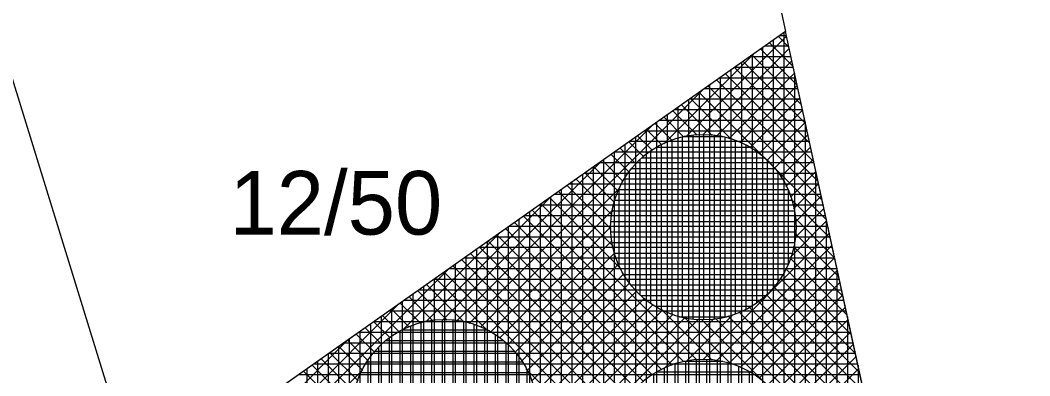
# Model space of a CAD drawing. Extents: x -566461 to -565198, y -1096301 to -1095707.
# Drawn here: x -566390.07 to -566371.02, y -1095849.12 to -1095842.41 of the extents above; entities that cross this region are included whole.
import ezdxf

# ---------------------------------------------------------------- set-up
doc = ezdxf.new("R2010")
doc.units = 0
for name, color, linetype in [('Vrstva 1', 7, 'Continuous'), ('Vrstva 40', 7, 'Continuous'), ('Vrstva 41', 7, 'Continuous'), ('Vrstva 42', 7, 'Continuous'), ('Vrstva 43', 7, 'Continuous'), ('Vrstva 44', 7, 'Continuous')]:
    doc.layers.add(name, color=color, linetype=linetype)

msp = doc.modelspace()

# ---------------------------------------------------------------- linework, layer by layer
at = {"layer": 'Vrstva 1'}
for p, q in [((-566376.68, -1095837.78), (-566375.63, -1095842.63)), ((-566387.83, -1095851.23), (-566391.07, -1095840.75)), ((-566375.63, -1095842.63), (-566387.83, -1095851.23)), ((-566371.02, -1095863.83), (-566375.63, -1095842.63))]:
    msp.add_line(p, q, dxfattribs=at)
at = {"layer": 'Vrstva 41'}
for p, q in [((-566375.611, -1095842.717), (-566377.507, -1095844.612)), ((-566375.763, -1095842.724), (-566375.567, -1095842.92)), ((-566375.561, -1095842.949), (-566377.192, -1095844.581)), ((-566376.095, -1095842.958), (-566375.41, -1095843.643)), ((-566375.929, -1095842.841), (-566375.488, -1095843.282)), ((-566376.231, -1095843.053), (-566377.927, -1095844.75)), ((-566376.261, -1095843.075), (-566375.331, -1095844.005)), ((-566375.51, -1095843.181), (-566376.929, -1095844.6)), ((-566376.593, -1095843.309), (-566375.174, -1095844.728)), ((-566376.427, -1095843.192), (-566375.252, -1095844.366)), ((-566376.759, -1095843.426), (-566375.095, -1095845.089)), ((-566375.46, -1095843.414), (-566376.696, -1095844.65)), ((-566377.09, -1095843.66), (-566374.938, -1095845.812)), ((-566376.925, -1095843.543), (-566375.017, -1095845.45)), ((-566375.409, -1095843.646), (-566376.487, -1095844.724)), ((-566377.189, -1095843.729), (-566381.595, -1095848.135)), ((-566377.422, -1095843.893), (-566376.654, -1095844.662)), ((-566377.256, -1095843.776), (-566374.859, -1095846.173)), ((-566375.359, -1095843.878), (-566376.3, -1095844.82)), ((-566377.588, -1095844.01), (-566377.01, -1095844.588)), ((-566377.92, -1095844.244), (-566377.545, -1095844.619)), ((-566377.754, -1095844.127), (-566377.296, -1095844.586)), ((-566375.308, -1095844.111), (-566376.131, -1095844.933)), ((-566378.148, -1095844.405), (-566381.83, -1095848.087)), ((-566378.252, -1095844.478), (-566377.962, -1095844.768)), ((-566378.086, -1095844.361), (-566377.764, -1095844.683)), ((-566375.257, -1095844.343), (-566375.979, -1095845.064)), ((-566378.418, -1095844.595), (-566378.141, -1095844.872)), ((-566375.207, -1095844.575), (-566375.842, -1095845.211)), ((-566378.749, -1095844.829), (-566378.448, -1095845.131)), ((-566378.584, -1095844.712), (-566378.302, -1095844.993)), ((-566375.156, -1095844.808), (-566375.722, -1095845.374)), ((-566378.915, -1095844.946), (-566378.577, -1095845.284)), ((-566375.106, -1095845.04), (-566375.62, -1095845.554)), ((-566379.106, -1095845.08), (-566382.098, -1095848.072)), ((-566379.247, -1095845.18), (-566378.782, -1095845.645)), ((-566379.081, -1095845.063), (-566378.689, -1095845.455)), ((-566379.579, -1095845.414), (-566378.903, -1095846.089)), ((-566379.413, -1095845.297), (-566378.855, -1095845.855)), ((-566375.055, -1095845.272), (-566375.536, -1095845.753)), ((-566378.75, -1095845.573), (-566381.385, -1095848.207)), ((-566379.745, -1095845.531), (-566378.918, -1095846.357)), ((-566375.005, -1095845.505), (-566375.475, -1095845.975)), ((-566380.065, -1095845.756), (-566382.416, -1095848.107)), ((-566380.077, -1095845.765), (-566378.725, -1095847.117)), ((-566379.911, -1095845.648), (-566378.883, -1095846.675)), ((-566375.522, -1095845.794), (-566374.781, -1095846.535)), ((-566374.954, -1095845.737), (-566375.445, -1095846.227)), ((-566378.888, -1095845.993), (-566381.195, -1095848.301)), ((-566380.408, -1095845.998), (-566377.546, -1095848.861)), ((-566380.243, -1095845.881), (-566377.296, -1095848.828)), ((-566374.904, -1095845.969), (-566375.462, -1095846.527)), ((-566380.574, -1095846.115), (-566377.765, -1095848.925)), ((-566374.853, -1095846.202), (-566375.534, -1095846.883)), ((-566375.448, -1095846.15), (-566374.702, -1095846.896)), ((-566378.919, -1095846.308), (-566381.024, -1095848.413)), ((-566380.906, -1095846.349), (-566378.141, -1095849.114)), ((-566380.74, -1095846.232), (-566377.962, -1095849.01)), ((-566381.023, -1095846.432), (-566382.857, -1095848.266)), ((-566381.238, -1095846.583), (-566378.448, -1095849.373)), ((-566381.072, -1095846.466), (-566378.303, -1095849.235)), ((-566378.9, -1095846.571), (-566380.87, -1095848.542)), ((-566374.803, -1095846.434), (-566377.191, -1095848.823)), ((-566375.452, -1095846.43), (-566374.624, -1095847.258)), ((-566381.404, -1095846.7), (-566378.577, -1095849.527)), ((-566374.752, -1095846.666), (-566376.928, -1095848.842)), ((-566375.479, -1095846.685), (-566374.545, -1095847.619)), ((-566381.736, -1095846.934), (-566378.781, -1095849.888)), ((-566381.57, -1095846.817), (-566378.689, -1095849.698)), ((-566378.85, -1095846.804), (-566380.733, -1095848.687)), ((-566374.702, -1095846.899), (-566376.696, -1095848.893)), ((-566375.543, -1095846.904), (-566374.467, -1095847.981)), ((-566381.982, -1095847.107), (-566387.422, -1095852.548)), ((-566381.902, -1095847.051), (-566378.853, -1095850.099)), ((-566378.776, -1095847.013), (-566380.612, -1095848.849)), ((-566374.651, -1095847.131), (-566376.487, -1095848.967)), ((-566375.628, -1095847.102), (-566374.388, -1095848.342)), ((-566382.233, -1095847.285), (-566381.242, -1095848.277)), ((-566382.067, -1095847.168), (-566378.902, -1095850.334)), ((-566378.68, -1095847.2), (-566380.508, -1095849.028)), ((-566375.732, -1095847.281), (-566374.309, -1095848.703)), ((-566382.565, -1095847.519), (-566382.011, -1095848.072)), ((-566382.399, -1095847.402), (-566381.691, -1095848.11)), ((-566378.567, -1095847.369), (-566380.423, -1095849.225)), ((-566378.436, -1095847.521), (-566380.359, -1095849.444)), ((-566374.601, -1095847.363), (-566376.3, -1095849.062)), ((-566375.853, -1095847.442), (-566374.231, -1095849.065)), ((-566382.731, -1095847.636), (-566382.281, -1095848.085)), ((-566378.289, -1095847.658), (-566380.326, -1095849.694)), ((-566376.144, -1095847.717), (-566374.193, -1095849.668)), ((-566374.55, -1095847.596), (-566376.131, -1095849.176)), ((-566375.991, -1095847.588), (-566374.152, -1095849.426)), ((-566382.94, -1095847.783), (-566387.489, -1095852.332)), ((-566383.063, -1095847.87), (-566382.728, -1095848.205)), ((-566382.897, -1095847.753), (-566382.516, -1095848.133)), ((-566377.946, -1095847.88), (-566380.402, -1095850.336)), ((-566378.126, -1095847.778), (-566380.339, -1095849.99)), ((-566377.977, -1095847.865), (-566377.011, -1095848.83)), ((-566376.315, -1095847.829), (-566374.251, -1095849.893)), ((-566374.5, -1095847.828), (-566375.978, -1095849.307)), ((-566377.273, -1095848.055), (-566386.086, -1095856.868)), ((-566383.395, -1095848.103), (-566383.09, -1095848.408)), ((-566377.525, -1095848.025), (-566383.378, -1095853.878)), ((-566377.747, -1095847.964), (-566383.233, -1095853.45)), ((-566383.229, -1095847.986), (-566382.918, -1095848.297)), ((-566376.983, -1095848.049), (-566377.927, -1095848.993)), ((-566377.535, -1095848.023), (-566376.654, -1095848.904)), ((-566376.617, -1095847.966), (-566377.506, -1095848.854)), ((-566377.217, -1095848.058), (-566374.562, -1095850.713)), ((-566376.949, -1095848.043), (-566374.449, -1095850.544)), ((-566376.715, -1095847.995), (-566374.367, -1095850.343)), ((-566376.505, -1095847.922), (-566374.309, -1095850.118)), ((-566374.449, -1095848.06), (-566375.842, -1095849.453)), ((-566383.561, -1095848.22), (-566383.244, -1095848.536)), ((-566374.399, -1095848.293), (-566375.723, -1095849.617)), ((-566383.899, -1095848.459), (-566387.556, -1095852.116)), ((-566383.892, -1095848.454), (-566383.504, -1095848.843)), ((-566383.726, -1095848.337), (-566383.382, -1095848.681)), ((-566384.058, -1095848.571), (-566383.608, -1095849.021)), ((-566374.348, -1095848.525), (-566375.621, -1095849.797)), ((-566384.39, -1095848.805), (-566383.759, -1095849.436)), ((-566384.224, -1095848.688), (-566383.694, -1095849.218)), ((-566374.298, -1095848.757), (-566375.537, -1095849.997)), ((-566383.604, -1095849.013), (-566387.355, -1095852.764)), ((-566384.722, -1095849.039), (-566383.792, -1095849.969)), ((-566384.556, -1095848.922), (-566383.794, -1095849.684)), ((-566380.527, -1095848.992), (-566378.916, -1095850.602)), ((-566374.247, -1095848.989), (-566375.477, -1095850.219))]:
    msp.add_line(p, q, dxfattribs=at)
at = {"layer": 'Vrstva 42'}
msp.add_lwpolyline([(-566383.841, -1095864.127), (-566382.67, -1095860.71), (-566381.61, -1095858.96), (-566380.13, -1095856.89), (-566378.22, -1095854.98), (-566377.21, -1095854.03), (-566376.26, -1095853.18), (-566375.36, -1095851.91), (-566374.4, -1095850.47), (-566374.143, -1095849.47), (-566375.63, -1095842.63), (-566387.83, -1095851.23)], close=True, dxfattribs=at)
at = {"layer": 'Vrstva 43'}
for p, q in [((-566375.729, -1095842.7), (-566375.615, -1095842.7)), ((-566375.66, -1095842.651), (-566375.66, -1095867.101)), ((-566376.06, -1095842.933), (-566376.06, -1095867.383)), ((-566376.013, -1095842.9), (-566375.571, -1095842.9)), ((-566375.86, -1095842.792), (-566375.86, -1095867.242)), ((-566376.297, -1095843.1), (-566375.528, -1095843.1)), ((-566376.26, -1095843.074), (-566376.26, -1095867.524)), ((-566376.58, -1095843.3), (-566375.484, -1095843.3)), ((-566376.46, -1095843.215), (-566376.46, -1095867.665)), ((-566376.864, -1095843.5), (-566375.441, -1095843.5)), ((-566376.86, -1095843.497), (-566376.86, -1095867.947)), ((-566376.66, -1095843.356), (-566376.66, -1095867.806)), ((-566375.46, -1095843.412), (-566375.46, -1095866.96)), ((-566377.148, -1095843.7), (-566375.397, -1095843.7)), ((-566377.06, -1095843.638), (-566377.06, -1095868.088)), ((-566377.432, -1095843.9), (-566375.354, -1095843.9)), ((-566377.26, -1095843.779), (-566377.26, -1095868.229)), ((-566377.715, -1095844.1), (-566375.31, -1095844.1)), ((-566377.66, -1095844.061), (-566377.66, -1095868.511)), ((-566377.46, -1095843.92), (-566377.46, -1095868.37)), ((-566377.86, -1095844.202), (-566377.86, -1095868.652)), ((-566378.26, -1095844.484), (-566378.26, -1095868.934)), ((-566378.06, -1095844.343), (-566378.06, -1095868.793)), ((-566377.999, -1095844.3), (-566375.267, -1095844.3)), ((-566375.26, -1095844.332), (-566375.26, -1095866.819)), ((-566378.46, -1095844.625), (-566378.46, -1095869.075)), ((-566378.283, -1095844.5), (-566375.223, -1095844.5)), ((-566378.66, -1095844.766), (-566378.66, -1095869.216)), ((-566378.567, -1095844.7), (-566375.18, -1095844.7)), ((-566379.06, -1095845.048), (-566379.06, -1095869.498)), ((-566378.86, -1095844.907), (-566378.86, -1095869.357)), ((-566378.85, -1095844.9), (-566375.136, -1095844.9)), ((-566379.26, -1095845.189), (-566379.26, -1095869.639)), ((-566379.134, -1095845.1), (-566375.093, -1095845.1)), ((-566379.46, -1095845.33), (-566379.46, -1095869.78)), ((-566379.418, -1095845.3), (-566375.049, -1095845.3)), ((-566375.06, -1095845.251), (-566375.06, -1095866.678)), ((-566379.86, -1095845.612), (-566379.86, -1095870.062)), ((-566379.701, -1095845.5), (-566375.006, -1095845.5)), ((-566379.66, -1095845.471), (-566379.66, -1095869.921)), ((-566380.06, -1095845.753), (-566380.06, -1095870.203)), ((-566379.985, -1095845.7), (-566374.962, -1095845.7)), ((-566380.269, -1095845.9), (-566374.919, -1095845.9)), ((-566380.26, -1095845.894), (-566380.26, -1095870.344)), ((-566380.66, -1095846.176), (-566380.66, -1095870.626)), ((-566380.553, -1095846.1), (-566374.875, -1095846.1)), ((-566380.46, -1095846.035), (-566380.46, -1095870.485)), ((-566374.86, -1095846.171), (-566374.86, -1095866.537)), ((-566380.86, -1095846.317), (-566380.86, -1095870.767)), ((-566380.836, -1095846.3), (-566374.832, -1095846.3)), ((-566381.12, -1095846.5), (-566374.788, -1095846.5)), ((-566381.06, -1095846.458), (-566381.06, -1095870.908)), ((-566381.46, -1095846.74), (-566381.46, -1095871.19)), ((-566381.404, -1095846.7), (-566374.745, -1095846.7)), ((-566381.26, -1095846.599), (-566381.26, -1095871.049)), ((-566381.687, -1095846.9), (-566374.701, -1095846.9)), ((-566381.66, -1095846.881), (-566381.66, -1095871.331)), ((-566381.971, -1095847.1), (-566374.658, -1095847.1)), ((-566381.86, -1095847.022), (-566381.86, -1095871.472)), ((-566374.66, -1095847.091), (-566374.66, -1095866.396)), ((-566382.26, -1095847.304), (-566382.26, -1095871.754)), ((-566382.255, -1095847.3), (-566374.614, -1095847.3)), ((-566382.06, -1095847.163), (-566382.06, -1095871.613)), ((-566382.539, -1095847.5), (-566374.571, -1095847.5)), ((-566382.46, -1095847.445), (-566382.46, -1095871.895)), ((-566382.822, -1095847.7), (-566374.528, -1095847.7)), ((-566382.66, -1095847.586), (-566382.66, -1095872.036)), ((-566383.106, -1095847.9), (-566374.484, -1095847.9)), ((-566383.06, -1095847.868), (-566383.06, -1095866.651)), ((-566382.86, -1095847.727), (-566382.86, -1095867.298)), ((-566383.39, -1095848.1), (-566374.441, -1095848.1)), ((-566383.26, -1095848.009), (-566383.26, -1095866.004)), ((-566374.46, -1095848.01), (-566374.46, -1095866.255)), ((-566383.66, -1095848.29), (-566383.66, -1095864.711)), ((-566383.46, -1095848.15), (-566383.46, -1095865.358)), ((-566383.86, -1095848.431), (-566383.86, -1095864.065)), ((-566383.673, -1095848.3), (-566374.397, -1095848.3)), ((-566384.06, -1095848.572), (-566384.06, -1095863.418)), ((-566383.957, -1095848.5), (-566374.354, -1095848.5)), ((-566384.46, -1095848.854), (-566384.46, -1095862.125)), ((-566384.26, -1095848.713), (-566384.26, -1095862.772)), ((-566384.241, -1095848.7), (-566374.31, -1095848.7)), ((-566384.66, -1095848.995), (-566384.66, -1095861.478)), ((-566384.525, -1095848.9), (-566374.267, -1095848.9)), ((-566374.26, -1095848.93), (-566374.26, -1095866.114)), ((-566384.808, -1095849.1), (-566374.223, -1095849.1))]:
    msp.add_line(p, q, dxfattribs=at)
msp.add_lwpolyline([(-566375.63, -1095842.63), (-566387.83, -1095851.23), (-566382.85, -1095867.33), (-566382.87, -1095870.81), (-566385.12, -1095873.77), (-566371.02, -1095863.83)], close=True, dxfattribs=at)
at = {"layer": 'Vrstva 44'}
for p, q in [((-566377.77, -1095847.966), (-566377.77, -1095844.674)), ((-566377.57, -1095848.026), (-566377.57, -1095844.616)), ((-566377.544, -1095844.61), (-566376.811, -1095844.61)), ((-566377.37, -1095848.059), (-566377.37, -1095844.582)), ((-566377.17, -1095848.068), (-566377.17, -1095844.571)), ((-566376.97, -1095848.055), (-566376.97, -1095844.583)), ((-566376.77, -1095848.02), (-566376.77, -1095844.621)), ((-566378.061, -1095844.81), (-566376.299, -1095844.81)), ((-566377.97, -1095847.881), (-566377.97, -1095844.759)), ((-566376.57, -1095847.96), (-566376.57, -1095844.682)), ((-566376.37, -1095847.869), (-566376.37, -1095844.77)), ((-566378.37, -1095847.602), (-566378.37, -1095845.037)), ((-566378.338, -1095845.01), (-566376.023, -1095845.01)), ((-566378.17, -1095847.761), (-566378.17, -1095844.879)), ((-566376.17, -1095847.747), (-566376.17, -1095844.893)), ((-566375.97, -1095847.582), (-566375.97, -1095845.057)), ((-566378.53, -1095845.21), (-566375.828, -1095845.21)), ((-566378.674, -1095845.41), (-566375.688, -1095845.41)), ((-566378.57, -1095847.38), (-566378.57, -1095845.259)), ((-566375.77, -1095847.355), (-566375.77, -1095845.286)), ((-566378.778, -1095845.61), (-566375.581, -1095845.61)), ((-566378.77, -1095847.05), (-566378.77, -1095845.59)), ((-566378.852, -1095845.81), (-566375.507, -1095845.81)), ((-566375.57, -1095847.001), (-566375.57, -1095845.636)), ((-566378.901, -1095846.01), (-566375.46, -1095846.01)), ((-566378.926, -1095846.21), (-566375.435, -1095846.21)), ((-566378.927, -1095846.41), (-566375.434, -1095846.41)), ((-566378.904, -1095846.61), (-566375.454, -1095846.61)), ((-566378.858, -1095846.81), (-566375.502, -1095846.81)), ((-566378.787, -1095847.01), (-566375.574, -1095847.01)), ((-566378.686, -1095847.21), (-566375.674, -1095847.21)), ((-566378.547, -1095847.41), (-566375.813, -1095847.41)), ((-566378.36, -1095847.61), (-566375.998, -1095847.61)), ((-566378.095, -1095847.81), (-566376.263, -1095847.81)), ((-566382.3, -1095851.542), (-566382.3, -1095848.078)), ((-566382.1, -1095851.559), (-566382.1, -1095848.062)), ((-566381.9, -1095851.551), (-566381.9, -1095848.069)), ((-566381.7, -1095851.521), (-566381.7, -1095848.098)), ((-566377.631, -1095848.01), (-566376.727, -1095848.01)), ((-566382.9, -1095851.344), (-566382.9, -1095848.277)), ((-566382.87, -1095848.26), (-566381.249, -1095848.26)), ((-566382.7, -1095851.438), (-566382.7, -1095848.182)), ((-566382.5, -1095851.503), (-566382.5, -1095848.118)), ((-566381.5, -1095851.466), (-566381.5, -1095848.154)), ((-566381.3, -1095851.386), (-566381.3, -1095848.236)), ((-566383.171, -1095848.46), (-566380.947, -1095848.46)), ((-566383.1, -1095851.215), (-566383.1, -1095848.404)), ((-566381.1, -1095851.271), (-566381.1, -1095848.347)), ((-566383.378, -1095848.66), (-566380.743, -1095848.66)), ((-566383.3, -1095851.043), (-566383.3, -1095848.578)), ((-566380.9, -1095851.119), (-566380.9, -1095848.502)), ((-566383.527, -1095848.86), (-566380.592, -1095848.86)), ((-566383.5, -1095850.803), (-566383.5, -1095848.818)), ((-566380.7, -1095850.908), (-566380.7, -1095848.71)), ((-566377.544, -1095848.85), (-566376.811, -1095848.85)), ((-566377.51, -1095852.277), (-566377.51, -1095848.842)), ((-566377.31, -1095852.303), (-566377.31, -1095848.815)), ((-566377.11, -1095852.307), (-566377.11, -1095848.813)), ((-566376.91, -1095852.288), (-566376.91, -1095848.833)), ((-566380.5, -1095850.6), (-566380.5, -1095849.021)), ((-566378.061, -1095849.05), (-566376.299, -1095849.05)), ((-566377.91, -1095852.148), (-566377.91, -1095848.972)), ((-566377.71, -1095852.226), (-566377.71, -1095848.894)), ((-566376.71, -1095852.245), (-566376.71, -1095848.876)), ((-566376.51, -1095852.175), (-566376.51, -1095848.944)), ((-566376.31, -1095852.077), (-566376.31, -1095849.044)), ((-566383.641, -1095849.06), (-566380.481, -1095849.06)), ((-566378.11, -1095852.041), (-566378.11, -1095849.078))]:
    msp.add_line(p, q, dxfattribs=at)
for centre in [(-566377.18, -1095846.32), (-566382.06, -1095849.81), (-566377.18, -1095850.56)]:
    msp.add_circle(centre, 1.75, dxfattribs=at)

# ---------------------------------------------------------------- texts
at = {"layer": 'Vrstva 40'}
msp.add_text('12/50', height=1.2, dxfattribs=at).set_placement((-566386.12, -1095846.46))

doc.saveas('drawing.dxf')
